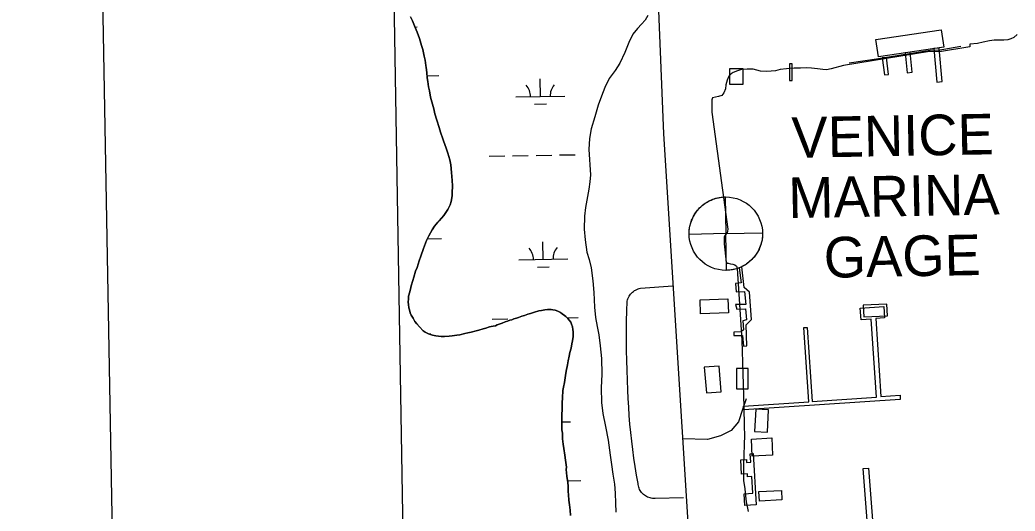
# Model space of a CAD drawing. Extents: x 3903937 to 3942190, y 260677 to 286651.
# Drawn here: x 3907281 to 3909314, y 274205 to 275208 of the extents above; entities that cross this region are included whole.
import ezdxf

# ---------------------------------------------------------------- set-up
doc = ezdxf.new("R2010")
doc.units = 0
for name, color, linetype in [('V-ANNO-SYMB', 7, 'Continuous'), ('V-BLDG-OTLN', 7, 'Continuous'), ('V-CHAN-DOCK', 7, 'Continuous'), ('V-GRID-FRAM', 7, 'Continuous'), ('V-RIVR-GAGE', 7, 'Continuous'), ('V-RIVR-GAGE-IDEN', 7, 'Continuous'), ('V-ROAD-CNTR', 7, 'Continuous'), ('V-RRAP-FSHR', 7, 'Continuous'), ('V-TOPO-SHOR', 7, 'Continuous'), ('V-WETL-SWMP', 7, 'Continuous')]:
    doc.layers.add(name, color=color, linetype=linetype)

msp = doc.modelspace()

# ---------------------------------------------------------------- linework, layer by layer
at = {"layer": 'V-ANNO-SYMB'}
msp.add_lwpolyline([(3907684.5, 261933.3), (3940762.5, 262515.6), (3940359.2, 285428.6), (3907281.2, 284846.4), (3907684.5, 261933.3)], dxfattribs=at)
at = {"layer": 'V-BLDG-OTLN'}
for points in [[(3909035.5, 275132.2), (3909030.1, 275167.6), (3909163.1, 275187.7), (3909168.5, 275152.3)], [(3908731.9, 275108.4), (3908758.1, 275108.4), (3908758.1, 275075.6), (3908731.9, 275075.6)], [(3908670.7, 274636), (3908727.5, 274638.2), (3908728.6, 274609.8), (3908671.7, 274607.7)], [(3909005.2, 274601.1), (3909053.4, 274603.2), (3909052.2, 274627.5), (3909004.1, 274625.4)], [(3908679.4, 274498.3), (3908683.8, 274445.8), (3908714.2, 274448.3), (3908709.8, 274500.8)], [(3908745, 274496.1), (3908745, 274454.5), (3908769.1, 274454.5), (3908769.1, 274496.1)], [(3908784.4, 274413), (3908782.2, 274367.1), (3908808.4, 274365.8), (3908810.6, 274411.7)], [(3908775.6, 274351.8), (3908817.2, 274353.9), (3908819, 274319.1), (3908777.5, 274316.9)], [(3908790.9, 274244.6), (3908836.9, 274246.8), (3908837.8, 274227.3), (3908791.9, 274225.1)]]:
    msp.add_lwpolyline(points, close=True, dxfattribs=at)
at = {"layer": 'V-CHAN-DOCK'}
for points in [[(3909104.1, 275100.7), (3909100.2, 275141.5), (3909089.7, 275140.5), (3909093.7, 275099.7), (3909104.1, 275100.7)], [(3909165.5, 275081.7), (3909159.3, 275150.3), (3909148.4, 275149.3), (3909154.6, 275080.7), (3909165.5, 275081.7)], [(3908858.8, 275083.8), (3908858.9, 275117.9), (3908853.8, 275117.9), (3908853.7, 275083.8), (3908858.8, 275083.8)], [(3909055.9, 275096.3), (3909051.7, 275131.2), (3909043.1, 275130.1), (3909047.3, 275095.3), (3909055.9, 275096.3)], [(3908739.6, 274563.1), (3908757.2, 274563.2), (3908759.4, 274541.3), (3908766.5, 274542.1), (3908765.2, 274585.3), (3908776.1, 274595.6), (3908772, 274651.6), (3908761, 274660.9), (3908756.2, 274703.2), (3908750.8, 274701.2), (3908754.6, 274671), (3908743.2, 274669.4), (3908744.6, 274652.5), (3908761.4, 274653.1), (3908764.4, 274626.8), (3908743.3, 274626.2), (3908746.1, 274616.8), (3908763.8, 274617.4), (3908765.5, 274595.1), (3908758.1, 274593.4), (3908759.5, 274574.6), (3908754.8, 274570.7), (3908739.5, 274570.1), (3908739.6, 274563.1)], [(3908759.5, 274418.8), (3908893.2, 274427.8), (3908883, 274579.2), (3908889.6, 274579.7), (3908899.8, 274428.5), (3909030.9, 274437.4), (3909020.2, 274596.7), (3908999.7, 274595.3), (3908998.1, 274619.3), (3909046.3, 274622.6), (3909047.8, 274599.4), (3909029.6, 274598.2), (3909040.3, 274438.8), (3909079.3, 274441.4), (3909079.9, 274432.7), (3908760.5, 274411.2), (3908759.5, 274418.8)], [(3908760.8, 274240.1), (3908778.4, 274241.1), (3908776.6, 274275.2), (3908767.9, 274274.7), (3908767.6, 274280.6), (3908755.7, 274280), (3908754.1, 274309.3), (3908765.5, 274309.9), (3908765.8, 274304.1), (3908774.2, 274304.5), (3908773.3, 274321.7), (3908779.5, 274322.1), (3908785.2, 274217.2), (3908762.1, 274215.9), (3908760.8, 274240.1)], [(3908776.2, 274043.3), (3909021.9, 274062.1), (3909004.3, 274291.8), (3909015.2, 274292.6), (3909050.6, 273832.3), (3909038.4, 273831.4), (3909021.3, 274053.5), (3908776.6, 274034.7), (3908776.2, 274043.3)]]:
    msp.add_lwpolyline(points, dxfattribs=at)
at = {"layer": 'V-GRID-FRAM'}
msp.add_lwpolyline([(3907892.2, 284196.1), (3939773.2, 284757.2), (3940101.1, 266577.6), (3908204.3, 266016.2), (3907892.2, 284196.1)], dxfattribs=at)
at = {"layer": 'V-RIVR-GAGE'}
for points in [[(3908721.9, 274846.2), (3908723.4, 274771.2), (3908648.4, 274769.8), (3908648.4, 274771.9), (3908648.4, 274774.4), (3908648.6, 274777.4), (3908648.9, 274780.4), (3908649.3, 274783.2), (3908649.9, 274786.2), (3908650.4, 274788.8), (3908651.1, 274791.2), (3908651.8, 274793.6), (3908652.7, 274796.3), (3908653.6, 274798.7), (3908654.5, 274801), (3908655.7, 274803.5), (3908657.1, 274806.3), (3908658.4, 274808.6), (3908659.7, 274810.9), (3908662.1, 274814.4), (3908663.7, 274816.7), (3908665.9, 274819.4), (3908668, 274821.8), (3908669.8, 274823.7), (3908672.5, 274826.3), (3908674.8, 274828.4), (3908677.2, 274830.3), (3908680.3, 274832.6), (3908682.6, 274834.2), (3908685.2, 274835.8), (3908688.1, 274837.4), (3908690.7, 274838.8), (3908693.3, 274839.9), (3908696.9, 274841.4), (3908700.1, 274842.5), (3908703.3, 274843.5), (3908706.5, 274844.3), (3908709.9, 274845), (3908713.9, 274845.6), (3908716.9, 274845.9), (3908719.5, 274846.1)], [(3908724.8, 274696.2), (3908723.4, 274771.2), (3908798.4, 274772.7), (3908798.4, 274770), (3908798.2, 274766.9), (3908798, 274764.3), (3908797.8, 274761.7), (3908797.3, 274758.5), (3908796.7, 274755.5), (3908795.9, 274752.2), (3908795.3, 274750), (3908794.4, 274747.1), (3908793.3, 274744.2), (3908792.3, 274741.6), (3908791.2, 274739.1), (3908789.9, 274736.6), (3908788.6, 274734.3), (3908787, 274731.6), (3908785.6, 274729.3), (3908783.5, 274726.4), (3908781.4, 274723.8), (3908778.9, 274720.8), (3908776.6, 274718.4), (3908774.2, 274716.1), (3908772, 274714.2), (3908770.4, 274712.8), (3908767.8, 274710.8), (3908765.9, 274709.5), (3908763.5, 274707.8), (3908760.8, 274706.2), (3908758.1, 274704.8), (3908756, 274703.7), (3908753.8, 274702.7), (3908751.2, 274701.6), (3908748.5, 274700.6), (3908745.2, 274699.5), (3908742.1, 274698.6), (3908739.7, 274698), (3908736.9, 274697.5), (3908734.6, 274697.1), (3908731.8, 274696.7), (3908729.6, 274696.5), (3908727, 274696.3)]]:
    msp.add_lwpolyline(points, close=True, dxfattribs=at)
msp.add_circle((3908723.4, 274771.2), 75, dxfattribs=at)
at = {"layer": 'V-ROAD-CNTR'}
for points in [[(3908539.7, 275833.9), (3908558, 275646.6), (3908581.3, 275344.8), (3908596.1, 274975.2), (3908671, 273778.2), (3908682.9, 273514.6)], [(3908636.8, 274231.5), (3908578.8, 274230.5), (3908576.2, 274230.4), (3908573.7, 274230.6), (3908571.1, 274230.9), (3908568.6, 274231.4), (3908566.1, 274232.1), (3908563.7, 274233.1), (3908561.4, 274234.2), (3908559.1, 274235.5), (3908557, 274236.9), (3908555, 274238.5), (3908553.1, 274240.3), (3908551.4, 274242.3), (3908549.8, 274244.3), (3908548.5, 274246.5), (3908547.2, 274248.7), (3908546.2, 274251.1), (3908545.4, 274253.5), (3908544.7, 274256), (3908544.3, 274258.6), (3908544, 274261.2), (3908541, 274278.3), (3908538.2, 274295.6), (3908535.6, 274312.8), (3908533.3, 274330.1), (3908531.1, 274347.4), (3908529.3, 274364.8), (3908527.6, 274382.2), (3908526.2, 274399.6), (3908525, 274417), (3908524.1, 274434.4), (3908523.3, 274451.8), (3908522.3, 274472), (3908521.5, 274492.1), (3908520.9, 274512.3), (3908520.6, 274532.5), (3908520.4, 274552.6), (3908520.5, 274572.8), (3908520.8, 274593), (3908521.2, 274613.1), (3908522, 274633.3), (3908522.6, 274635.9), (3908523.5, 274638.4), (3908524.6, 274640.8), (3908525.9, 274643.2), (3908527.3, 274645.5), (3908528.9, 274647.6), (3908530.7, 274649.6), (3908532.6, 274651.5), (3908534.6, 274653.2), (3908536.8, 274654.8), (3908539.1, 274656.1), (3908541.5, 274657.3), (3908544, 274658.4), (3908546.5, 274659.2), (3908549.1, 274659.8), (3908615.3, 274664.7)], [(3908764.7, 274434.1), (3908757.4, 274412), (3908749.2, 274387.1), (3908734.1, 274369.1), (3908712.8, 274358.3), (3908685.7, 274351.1), (3908635.1, 274352.4)]]:
    msp.add_lwpolyline(points, dxfattribs=at)
at = {"layer": 'V-RRAP-FSHR'}
msp.add_lwpolyline([(3909203.7, 275153.6), (3909157, 275144.9), (3909145.2, 275146), (3909031, 275127.2), (3908975.3, 275119.6)], dxfattribs=at)
at = {"layer": 'V-TOPO-SHOR'}
for points in [[(3908079.5, 275214.3), (3908083.3, 275205.6), (3908089, 275192.1), (3908092.9, 275182.7), (3908097.4, 275169.6), (3908101.9, 275155.7), (3908104.1, 275147.1), (3908107.4, 275134), (3908108.9, 275125.8), (3908110.2, 275114.5), (3908110.9, 275110.8), (3908112.3, 275100.6), (3908113.2, 275089.6), (3908114.6, 275081.9), (3908116, 275070.9), (3908117.8, 275062.7), (3908120.3, 275050.1), (3908122.9, 275040.7), (3908127, 275026), (3908129.2, 275015.7), (3908133.3, 275003.1), (3908137.4, 274987.9), (3908140.4, 274978.5), (3908145.3, 274964.6), (3908146.8, 274960.5), (3908152.1, 274945.8), (3908155.5, 274935.9), (3908159.2, 274922), (3908161.8, 274911.8), (3908163, 274896), (3908164.2, 274879.7), (3908164.8, 274869.1), (3908164.4, 274854.5), (3908164.2, 274848.5), (3908162.3, 274836.7), (3908160.1, 274829.9), (3908155.4, 274820.3), (3908151.2, 274814.3), (3908147, 274808.3), (3908137.4, 274797.6), (3908135.3, 274794.8), (3908128.2, 274786.5), (3908123.1, 274778.9), (3908116.3, 274766.9), (3908112, 274756.9), (3908105.9, 274740.8), (3908100.2, 274725.5), (3908096.7, 274715.9), (3908092.7, 274702.2), (3908089.3, 274694.5), (3908086.1, 274682), (3908083.9, 274675.2), (3908080.8, 274664.7), (3908079.9, 274661.5), (3908077.6, 274652.2), (3908075.4, 274643.8), (3908074.8, 274638.1), (3908074.7, 274631.2), (3908074.9, 274626.3), (3908075.6, 274619.8), (3908077.1, 274615.3), (3908078.6, 274609.2), (3908080.5, 274604.7), (3908084.4, 274598.5), (3908088.3, 274591.9), (3908091.8, 274586.9), (3908097.3, 274580.7), (3908104.8, 274572.8), (3908108.8, 274569.8), (3908115.6, 274566.8), (3908124.1, 274564.2), (3908130.9, 274562.4), (3908141.9, 274560.9), (3908148.8, 274561.1), (3908158.5, 274561.7), (3908164.2, 274562.3), (3908174, 274563.7), (3908179.7, 274564.8), (3908189.9, 274567), (3908196.4, 274568.4), (3908203.4, 274570.3), (3908213.2, 274572.4), (3908218.9, 274573.9), (3908227.5, 274576.5), (3908233.2, 274578.4), (3908240.6, 274580.7), (3908244.2, 274581.4)], [(3909318.3, 275177.7), (3909312.1, 275171.7), (3909305.4, 275168.9), (3909299.5, 275167.3), (3909291.7, 275166), (3909281.5, 275166.3), (3909271.6, 275166.2), (3909261.8, 275165.3), (3909248.9, 275162.1), (3909237.5, 275159.6), (3909221.8, 275157.9), (3909221.8, 275152.7), (3909160.2, 275142.7), (3909139.7, 275142.9), (3908963.5, 275114.4), (3908938.8, 275107.5), (3908929.3, 275105.8), (3908921.9, 275106.6), (3908910.8, 275108), (3908898.6, 275109.1), (3908887.2, 275109.8), (3908876.2, 275109.3), (3908863.2, 275109.1), (3908847.1, 275107.8), (3908834.2, 275106.1), (3908825.1, 275104), (3908807.1, 275102.3), (3908794.1, 275103.3), (3908779.1, 275107.1), (3908766.9, 275107.4), (3908755.5, 275106.1), (3908747.3, 275103.7), (3908738.7, 275100), (3908734.4, 275097.6), (3908729.3, 275092.5), (3908725.9, 275084.6), (3908723.6, 275075.1), (3908722.5, 275066.9), (3908719.4, 275058.6), (3908715.5, 275053), (3908708.1, 275051.4), (3908696.3, 275048.9), (3908694.8, 275044.6), (3908694.8, 275038.3), (3908694.9, 275032.4), (3908695, 275019.4), (3908727.3, 274780.2), (3908726.9, 274776.3), (3908725.8, 274772.8), (3908725, 274771.6), (3908721.9, 274768.4), (3908720.3, 274764.5), (3908720, 274761.7), (3908720.1, 274750.3), (3908724.4, 274713), (3908726.8, 274711), (3908728.3, 274710.7), (3908732.7, 274709.5), (3908737.8, 274709.2), (3908741.7, 274707.6), (3908744.9, 274704.9), (3908746.9, 274700.2), (3908755.8, 274553.6), (3908759.9, 274417.2), (3908760.7, 274377.5), (3908761.7, 274359.8), (3908761.1, 274339.8), (3908760.1, 274319.3), (3908759.5, 274301.2), (3908759.7, 274278.8), (3908759.8, 274267), (3908761.9, 274250.1), (3908763.3, 274235.6), (3908765, 274223.4), (3908768.7, 274203.8)], [(3908244.2, 274581.4), (3908248.3, 274582.1), (3908252.8, 274583.2), (3908256.5, 274584.7), (3908262.2, 274587), (3908266.3, 274588.5), (3908272.5, 274590.8), (3908277, 274592.3), (3908282.3, 274594.2), (3908286, 274595.3), (3908290.1, 274596.9), (3908295.4, 274598.7), (3908299.9, 274599.9), (3908306.5, 274602.5), (3908311.8, 274604), (3908319.2, 274606.7), (3908324.1, 274607.8), (3908332.7, 274610.8), (3908341.3, 274613.4), (3908346.6, 274614.5), (3908353.5, 274615.9), (3908358.8, 274616.2), (3908366.5, 274616.4), (3908370.1, 274615.9), (3908374.6, 274615), (3908380.2, 274612.8), (3908385.4, 274610.2), (3908389, 274607.7), (3908393.8, 274604.3), (3908396.6, 274602.2), (3908400.9, 274597.7), (3908403.3, 274594.8), (3908406.4, 274590.6), (3908407.9, 274586.5), (3908409.8, 274581.2), (3908410.9, 274575.5), (3908411.6, 274571), (3908411.5, 274565.7), (3908411.3, 274560.9), (3908409.9, 274552.4), (3908408.5, 274546.3), (3908407.1, 274537.4), (3908404.8, 274528.6), (3908403.4, 274521.3), (3908401.1, 274511.2), (3908399.7, 274503.5), (3908397.4, 274490.6), (3908395.5, 274481.3), (3908393.5, 274467.2), (3908391.6, 274457.5), (3908390.7, 274450.6), (3908389.5, 274435.6), (3908388.8, 274425.9), (3908388.8, 274411.7), (3908388.6, 274402.8), (3908388.3, 274390.2), (3908388.1, 274382.1), (3908388.6, 274370.7), (3908389.6, 274363.4), (3908389.8, 274352.4), (3908391.1, 274341), (3908392.1, 274332.1), (3908394.2, 274318.6), (3908395.5, 274308.4), (3908397.6, 274294.2), (3908397.5, 274289.3), (3908398.8, 274275.9), (3908400.5, 274263.3), (3908401.1, 274255.5), (3908401.6, 274244.6), (3908402.3, 274238.1), (3908402.8, 274227.1), (3908403.8, 274217.3), (3908405.1, 274206.3), (3908406, 274195.8)]]:
    msp.add_lwpolyline(points, dxfattribs=at)
at = {"layer": 'V-WETL-SWMP'}
for p, q in [((3908083.3, 275205.6), (3908079.5, 275214.3)), ((3908089, 275192.1), (3908083.3, 275205.6)), ((3908551.3, 275198.9), (3908543.2, 275190.2)), ((3908558.3, 275206.9), (3908551.3, 275198.9)), ((3908564.1, 275216.7), (3908558.3, 275206.9)), ((3908088.6, 275193.2), (3908092.5, 275193.3)), ((3908092.9, 275182.7), (3908089, 275192.1)), ((3908097.4, 275169.6), (3908092.9, 275182.7)), ((3908543.2, 275190.2), (3908533.4, 275178.3)), ((3908101.9, 275155.7), (3908097.4, 275169.6)), ((3908525.4, 275161.3), (3908517.3, 275141.2)), ((3908533.4, 275178.3), (3908525.4, 275161.3)), ((3908104.1, 275147.1), (3908101.9, 275155.7)), ((3908107.4, 275134), (3908104.1, 275147.1)), ((3908517.3, 275141.2), (3908506.9, 275119.5)), ((3908108.8, 275125.8), (3908107.4, 275134)), ((3908110.2, 275114.5), (3908108.8, 275125.8)), ((3908506.9, 275119.5), (3908497.2, 275104.1)), ((3908110.9, 275110.8), (3908110.2, 275114.5)), ((3908112.3, 275100.6), (3908110.9, 275110.8)), ((3908113.2, 275089.6), (3908112.3, 275100.6)), ((3908497.2, 275104.1), (3908485.2, 275087.8)), ((3908112.9, 275093.6), (3908136.9, 275094.1)), ((3908114.6, 275081.9), (3908113.2, 275089.6)), ((3908116, 275070.9), (3908114.6, 275081.9)), ((3908344.5, 275051.3), (3908343.9, 275087.3)), ((3908485.2, 275087.8), (3908475.9, 275069.7)), ((3908117.8, 275062.7), (3908116, 275070.9)), ((3908120.3, 275050.1), (3908117.8, 275062.7)), ((3908475.9, 275069.7), (3908469.4, 275051.9)), ((3908122.9, 275040.7), (3908120.3, 275050.1)), ((3908127, 275026), (3908122.9, 275040.7)), ((3908294.5, 275050.4), (3908394.5, 275052.2)), ((3908332.8, 275035.6), (3908356.8, 275036.1)), ((3908469.4, 275051.9), (3908462.9, 275033.4)), ((3908129.2, 275015.7), (3908127, 275026)), ((3908133.3, 275003.1), (3908129.2, 275015.7)), ((3908462.9, 275033.4), (3908455.7, 275010.1)), ((3908137.4, 274987.9), (3908133.3, 275003.1)), ((3908455.7, 275010.1), (3908448.1, 274985.3)), ((3908140.4, 274978.5), (3908137.4, 274987.9)), ((3908145.3, 274964.6), (3908140.4, 274978.5)), ((3908448.1, 274985.3), (3908445.1, 274965.6)), ((3908146.8, 274960.5), (3908145.3, 274964.6)), ((3908152.1, 274945.8), (3908146.8, 274960.5)), ((3908445.1, 274965.6), (3908443.4, 274942.8)), ((3908155.5, 274935.9), (3908152.1, 274945.8)), ((3908159.2, 274922), (3908155.5, 274935.9)), ((3908443.4, 274942.8), (3908447, 274891)), ((3908161.8, 274911.8), (3908159.2, 274922)), ((3908239.8, 274929.3), (3908271.8, 274929.9)), ((3908287.8, 274930.2), (3908319.8, 274930.8)), ((3908335.8, 274931), (3908367.8, 274931.6)), ((3908383.8, 274931.9), (3908415.8, 274932.4)), ((3908163, 274896), (3908161.8, 274911.8)), ((3908164.2, 274879.7), (3908163, 274896)), ((3908164.8, 274869.1), (3908164.2, 274879.7)), ((3908445.6, 274876.8), (3908443.8, 274861.8)), ((3908447, 274891), (3908445.6, 274876.8)), ((3908164.2, 274848.5), (3908164.4, 274854.5)), ((3908164.4, 274854.5), (3908164.8, 274869.1)), ((3908443.8, 274861.8), (3908439.3, 274839.8)), ((3908160.1, 274829.9), (3908162.3, 274836.7)), ((3908162.3, 274836.7), (3908164.2, 274848.5)), ((3908439.3, 274839.8), (3908436.7, 274824.8)), ((3908147, 274808.3), (3908151.2, 274814.3)), ((3908151.2, 274814.3), (3908155.4, 274820.3)), ((3908155.4, 274820.3), (3908160.1, 274829.9)), ((3908436.7, 274824.8), (3908434.5, 274807.1)), ((3908128.2, 274786.5), (3908135.3, 274794.8)), ((3908135.3, 274794.8), (3908137.4, 274797.6)), ((3908137.4, 274797.6), (3908147, 274808.3)), ((3908434.5, 274807.1), (3908434, 274780.4)), ((3908116.3, 274766.9), (3908123.1, 274778.9)), ((3908123.1, 274778.9), (3908128.2, 274786.5)), ((3908434, 274780.4), (3908435.8, 274758.4)), ((3908105.9, 274740.8), (3908112, 274756.9)), ((3908112, 274756.9), (3908116.3, 274766.9)), ((3908113.7, 274760.9), (3908142.7, 274761.4)), ((3908350.4, 274718.7), (3908349.7, 274754.7)), ((3908435.8, 274758.4), (3908439.5, 274733.3)), ((3908100.2, 274725.5), (3908105.9, 274740.8)), ((3908439.5, 274733.3), (3908444, 274718.4)), ((3908092.7, 274702.2), (3908096.7, 274715.9)), ((3908096.7, 274715.9), (3908100.2, 274725.5)), ((3908300.4, 274717.8), (3908400.4, 274719.5)), ((3908444, 274718.4), (3908448.1, 274701.5)), ((3908086.1, 274682), (3908089.3, 274694.5)), ((3908089.3, 274694.5), (3908092.7, 274702.2)), ((3908338.6, 274703), (3908362.6, 274703.4)), ((3908448.1, 274701.5), (3908451.9, 274674.5)), ((3908080.8, 274664.7), (3908083.9, 274675.2)), ((3908083.9, 274675.2), (3908086.1, 274682)), ((3908451.9, 274674.5), (3908453.7, 274650.9)), ((3908075.4, 274643.8), (3908077.6, 274652.2)), ((3908077.6, 274652.2), (3908079.9, 274661.5)), ((3908079.9, 274661.5), (3908080.8, 274664.7)), ((3908453.7, 274650.9), (3908454.8, 274621)), ((3908074.7, 274631.2), (3908074.8, 274638.1)), ((3908074.9, 274626.3), (3908074.7, 274631.2)), ((3908074.8, 274638.1), (3908075.4, 274643.8)), ((3908075.6, 274619.8), (3908074.9, 274626.3)), ((3908077.1, 274615.3), (3908075.6, 274619.8)), ((3908078.6, 274609.2), (3908077.1, 274615.3)), ((3908080.5, 274604.7), (3908078.6, 274609.2)), ((3908332.7, 274610.8), (3908324.1, 274607.8)), ((3908341.3, 274613.4), (3908332.7, 274610.8)), ((3908346.6, 274614.5), (3908341.3, 274613.4)), ((3908353.5, 274615.9), (3908346.6, 274614.5)), ((3908358.8, 274616.2), (3908353.5, 274615.9)), ((3908366.5, 274616.4), (3908358.8, 274616.2)), ((3908370.1, 274615.9), (3908366.5, 274616.4)), ((3908374.6, 274615), (3908370.1, 274615.9)), ((3908380.2, 274612.8), (3908374.6, 274615)), ((3908385.4, 274610.2), (3908380.2, 274612.8)), ((3908389, 274607.7), (3908385.4, 274610.2)), ((3908454.8, 274621), (3908457.4, 274599.8)), ((3908084.4, 274598.5), (3908080.5, 274604.7)), ((3908088.3, 274591.9), (3908084.4, 274598.5)), ((3908091.8, 274586.9), (3908088.3, 274591.9)), ((3908245.7, 274596.7), (3908277.7, 274597.3)), ((3908272.5, 274590.8), (3908266.3, 274588.5)), ((3908277, 274592.3), (3908272.5, 274590.8)), ((3908282.3, 274594.2), (3908277, 274592.3)), ((3908286, 274595.3), (3908282.3, 274594.2)), ((3908290.1, 274596.9), (3908286, 274595.3)), ((3908295.4, 274598.7), (3908290.1, 274596.9)), ((3908299.9, 274599.8), (3908295.4, 274598.7)), ((3908306.5, 274602.5), (3908299.9, 274599.8)), ((3908311.8, 274604), (3908306.5, 274602.5)), ((3908319.2, 274606.7), (3908311.8, 274604)), ((3908324.1, 274607.8), (3908319.2, 274606.7)), ((3908393.8, 274604.3), (3908389, 274607.7)), ((3908396.6, 274602.2), (3908393.8, 274604.3)), ((3908400.9, 274597.7), (3908396.6, 274602.2)), ((3908399.2, 274599.4), (3908421.6, 274599.8)), ((3908403.3, 274594.8), (3908400.9, 274597.7)), ((3908406.4, 274590.6), (3908403.3, 274594.8)), ((3908407.9, 274586.5), (3908406.4, 274590.6)), ((3908457.4, 274599.8), (3908460.7, 274581.4)), ((3908097.3, 274580.7), (3908091.8, 274586.9)), ((3908104.8, 274572.8), (3908097.3, 274580.7)), ((3908108.8, 274569.8), (3908104.8, 274572.8)), ((3908115.6, 274566.8), (3908108.8, 274569.8)), ((3908196.4, 274568.4), (3908189.9, 274567)), ((3908203.4, 274570.3), (3908196.4, 274568.4)), ((3908213.2, 274572.4), (3908203.4, 274570.3)), ((3908218.9, 274573.9), (3908213.2, 274572.4)), ((3908227.5, 274576.5), (3908218.9, 274573.9)), ((3908233.2, 274578.4), (3908227.5, 274576.5)), ((3908240.6, 274580.7), (3908233.2, 274578.4)), ((3908244.2, 274581.4), (3908240.6, 274580.7)), ((3908248.3, 274582.1), (3908244.2, 274581.4)), ((3908252.8, 274583.2), (3908248.3, 274582.1)), ((3908256.5, 274584.7), (3908252.8, 274583.2)), ((3908262.2, 274587), (3908256.5, 274584.7)), ((3908266.3, 274588.5), (3908262.2, 274587)), ((3908409.8, 274581.2), (3908407.9, 274586.5)), ((3908410.9, 274575.5), (3908409.8, 274581.2)), ((3908411.6, 274571), (3908410.9, 274575.5)), ((3908411.5, 274565.7), (3908411.6, 274571)), ((3908460.7, 274581.4), (3908464, 274564.5)), ((3908124.1, 274564.2), (3908115.6, 274566.8)), ((3908130.9, 274562.4), (3908124.1, 274564.2)), ((3908141.9, 274560.9), (3908130.9, 274562.4)), ((3908148.8, 274561.1), (3908141.9, 274560.9)), ((3908158.5, 274561.7), (3908148.8, 274561.1)), ((3908164.2, 274562.3), (3908158.5, 274561.7)), ((3908174, 274563.7), (3908164.2, 274562.3)), ((3908179.7, 274564.8), (3908174, 274563.7)), ((3908189.9, 274567), (3908179.7, 274564.8)), ((3908408.5, 274546.3), (3908409.9, 274552.4)), ((3908409.9, 274552.4), (3908411.3, 274560.9)), ((3908411.3, 274560.9), (3908411.5, 274565.7)), ((3908464, 274564.5), (3908467, 274542.2)), ((3908403.4, 274521.3), (3908404.8, 274528.6)), ((3908404.8, 274528.6), (3908407.1, 274537.4)), ((3908407.1, 274537.4), (3908408.5, 274546.3)), ((3908467, 274542.2), (3908469.2, 274516.2)), ((3908399.7, 274503.5), (3908401.1, 274511.2)), ((3908401.1, 274511.2), (3908403.4, 274521.3)), ((3908469.2, 274516.2), (3908470.3, 274484.4)), ((3908395.5, 274481.3), (3908397.4, 274490.6)), ((3908397.4, 274490.6), (3908399.7, 274503.5)), ((3908391.6, 274457.5), (3908393.5, 274467.2)), ((3908393.5, 274467.2), (3908395.5, 274481.3)), ((3908470.3, 274484.4), (3908468.6, 274456.5)), ((3908389.5, 274435.6), (3908390.7, 274450.6)), ((3908390.7, 274450.6), (3908391.6, 274457.5)), ((3908468.6, 274456.5), (3908469.3, 274426.2)), ((3908388.8, 274425.9), (3908389.5, 274435.6)), ((3908469.3, 274426.2), (3908472.2, 274403.9)), ((3908388.6, 274402.8), (3908388.8, 274411.7)), ((3908388.8, 274411.7), (3908388.8, 274425.9)), ((3908388.1, 274382.1), (3908388.3, 274390.2)), ((3908388.2, 274386.6), (3908406.2, 274386.9)), ((3908388.3, 274390.2), (3908388.6, 274402.8)), ((3908472.2, 274403.9), (3908477.6, 274377.2)), ((3908388.6, 274370.7), (3908388.1, 274382.1)), ((3908389.6, 274363.4), (3908388.6, 274370.7)), ((3908477.6, 274377.2), (3908483, 274349.7)), ((3908389.8, 274352.4), (3908389.6, 274363.4)), ((3908391.1, 274341), (3908389.8, 274352.4)), ((3908483, 274349.7), (3908486.8, 274319.1)), ((3908392.1, 274332.1), (3908391.1, 274341)), ((3908394.2, 274318.6), (3908392.1, 274332.1)), ((3908395.5, 274308.4), (3908394.2, 274318.6)), ((3908397.6, 274294.2), (3908395.5, 274308.4)), ((3908486.8, 274319.1), (3908489.8, 274299.5)), ((3908397.5, 274289.3), (3908397.6, 274294.2)), ((3908398.8, 274275.9), (3908397.5, 274289.3)), ((3908489.8, 274299.5), (3908492.7, 274279.9)), ((3908400.5, 274263.3), (3908398.8, 274275.9)), ((3908400, 274266.7), (3908427.5, 274267.2)), ((3908492.7, 274279.9), (3908495.7, 274259.9)), ((3908401.1, 274255.5), (3908400.5, 274263.3)), ((3908401.6, 274244.6), (3908401.1, 274255.5)), ((3908402.3, 274238.1), (3908401.6, 274244.6)), ((3908495.7, 274259.9), (3908497, 274241)), ((3908402.8, 274227.1), (3908402.3, 274238.1)), ((3908403.8, 274217.3), (3908402.8, 274227.1)), ((3908497, 274241), (3908498, 274220.6)), ((3908405.1, 274206.3), (3908403.8, 274217.3)), ((3908406, 274195.8), (3908405.1, 274206.3)), ((3908498, 274220.6), (3908499, 274202.5))]:
    msp.add_line(p, q, dxfattribs=at)
for centre, start, end in [((3908289.3, 275050.8), 0.2366, 41.7802), ((3908399.7, 275052.7), 140.2366, 181.7802), ((3908295.1, 274718.2), 0.2366, 41.7802), ((3908405.6, 274720.1), 140.2366, 181.7802), ((3908147.2, 274544.7), 140.2366, 143.2871)]:
    msp.add_arc(centre, 35.2, start, end, dxfattribs=at)

# ---------------------------------------------------------------- texts
at = {"layer": 'V-RIVR-GAGE-IDEN'}
for s, p in [('VENICE', (3908858.3, 274925.9)), ('MARINA', (3908851.7, 274802.7)), ('GAGE', (3908924.2, 274681))]:
    msp.add_text(s, height=83, rotation=1.0252, dxfattribs=at).set_placement(p)

doc.saveas('drawing.dxf')
